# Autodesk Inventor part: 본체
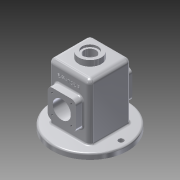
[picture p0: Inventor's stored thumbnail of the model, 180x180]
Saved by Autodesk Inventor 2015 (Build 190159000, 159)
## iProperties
Created: 2021-08
Part Number: 본체
Material: 알루미늄 6061
Document SubType Name: Modeling
Designer: 104-1
Density: 2.7 g/cm^3
Appearance: 알루미늄 - 평지
Mass: 822.027 g
Surface Area: 962.051 cm^2
Volume: 304.454 cm^3
Author: 104-1
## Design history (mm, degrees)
sketch "스케치1"
  geometry: L1 (37, 37)-(-37, 37); L2 (-37, 37)-(-37, -37); L3 (-37, -37)-(37, -37); L4 (37, -37)-(37, 37); L5 (37, 37)-(-37, -37); L6 (-37, 37)-(37, -37); 1 further point
  constraints: 12 end point, 2 midpoint, 2 parallel, 1 horizontal, 1 perpendicular
  dimensions: "d0" = 74 distance of L2.end L3.end; "d1" = 74 distance of L3.end L1.start
extrude "돌출1" new body sketch "스케치1" distance "d2" = 110; taper "d3" = 0 deg
fillet "모깎기1" dims "d4" = 8
fillet "모깎기2" dims "d5" = 8
feature "쉘1" dims "d6" = 5
sketch "스케치2"
  geometry: L1 (-29, 37)-(29, 37) reference; L2 (-37, -29)-(-37, 29) reference; L3 (29, -37)-(-29, -37) reference; L4 (37, 29)-(37, -29) reference; C1 r 67 at (0, 0); A1 r 8 centre (29, 29) between (37, 29) and (29, 37) reference; A2 r 8 centre (-29, 29) between (-29, 37) and (-37, 29) reference; A3 r 8 centre (-29, -29) between (-37, -29) and (-29, -37) reference; A4 r 8 centre (29, -29) between (29, -37) and (37, -29) reference; 1 further point
  constraints: 1 centre point, 1 coincident
  dimensions: "d7" = 134 diameter of C1
extrude "돌출2" join sketch "스케치2" distance "d8" = 10; taper "d9" = 0 deg
sketch "스케치3"
  geometry: L1 (54, -22)-(4, -22); L2 (4, -22)-(4, -72); L3 (4, -72)-(54, -72); L4 (54, -72)-(54, -22); L5 (54, -22)-(4, -72); L6 (4, -22)-(54, -72); L7 (96, -102)-(-38, -102) reference; 4 further points
  constraints: 12 end point, 4 midpoint, 2 parallel, 1 horizontal, 1 perpendicular, 1 vertical alignment
  dimensions: "d10" = 55 distance from line of L7 point (29, -47); "d61" = 50 distance of L1.end L2.end; "d62" = 50 distance of L2.end L3.end
extrude "돌출3" join sketch "스케치3" distance "d11" = 13; taper "d13" = 0 deg; dims "d12" = 12, "d14" = 0
chamfer "모따기1" distance "d15" = 7; stored, may be unused: second distance "d16" = 2, angle "d17" = 20 deg
chamfer "모따기2" distance "d18" = 7; stored, may be unused: second distance "d19" = 2, angle "d20" = 20 deg
chamfer "모따기3" distance "d21" = 7; stored, may be unused: second distance "d22" = 2, angle "d23" = 20 deg
chamfer "모따기4" distance "d24" = 7; stored, may be unused: second distance "d25" = 2, angle "d26" = 20 deg
chamfer "모따기5" distance "d27" = 7; stored, may be unused: second distance "d28" = 2, angle "d29" = 20 deg
chamfer "모따기6" distance "d30" = 7; stored, may be unused: second distance "d31" = 2, angle "d32" = 20 deg
chamfer "모따기7" distance "d33" = 7; stored, may be unused: second distance "d34" = 2, angle "d35" = 20 deg
fillet "모깎기3" dims "d36" = 8
fillet "모깎기4" dims "d37" = 8
chamfer "모따기8" distance "d38" = 7; stored, may be unused: second distance "d39" = 2, angle "d40" = 45 deg
sketch "스케치4"
  geometry: C1 r 67 at (0, 0) reference; 1 further point
  constraints: 1 horizontal alignment
  dimensions: "d41" = 55 distance of C1.centre point (-55, 0)
hole "구멍1" sketch "스케치4" at (-55, 0) diameter "d42" = 9; stored, may be unused: countersink angle "d46" = 90 deg, drill point angle "d48" = 118 deg; dims "d43" = 6, "d44" = 4, "d45" = 2, "d47" = 8
sketch "스케치5"
  geometry: L1 (96, -102)-(-38, -102) reference; L2 (-8, 0)-(-8, -92) reference; 2 further points
  dimensions: "d52" = 55 distance from line of L1 point (29, -47); "d53" = 37 distance from line of L2 point (29, -47)
hole "구멍2" sketch "스케치5" at (29, -47) diameter "d54" = 32; stored, may be unused: countersink angle "d58" = 90 deg, drill point angle "d60" = 118 deg; dims "d55" = 6, "d56" = 4, "d57" = 2, "d59" = 8
sketch "스케치6"
  geometry: A1 r 8 centre (34, -42) between (34, -50) and (42, -42) reference; A2 r 8 centre (34, -8) between (42, -8) and (34, 0) reference; A3 r 8 centre (0, -8) between (0, 0) and (-8, -8) reference; A4 r 8 centre (0, -42) between (-8, -42) and (0, -50) reference; 1 further point
hole "구멍3" sketch "스케치6" at (34, -42), (0, -8), (34, -8), (0, -42) diameter "d63" = 3.242; stored, may be unused: countersink angle "d67" = 90 deg, drill point angle "d69" = 118 deg; dims "d64" = 8, "d65" = 4, "d66" = 2, "d68" = 10
node "작업 평면1"
sketch "스케치8"
  geometry: L1 (29, 29)-(29, -29) reference; L2 (-29, 29)-(29, 29) reference; L3 (-29, -29)-(-29, 29) reference; L4 (29, -29)-(-29, -29) reference; L5 (37, -29)-(37, 29) reference; L6 (29, 37)-(-29, 37) reference; L7 (-37, 29)-(-37, -29) reference; L8 (-29, -37)-(29, -37) reference; C1 r 20 at (0, 0); 1 further point
  constraints: 1 centre point, 1 coincident
  dimensions: "d71" = 40 diameter of C1
extrude "돌출4" join sketch "스케치8" stored distance "d72" = 13; taper "d73" = 0 deg
sketch "스케치9"
  geometry: C1 r 20 at (0, 0) reference
hole "구멍4" sketch "스케치9" at (0, 0) diameter "d74" = 21; stored, may be unused: countersink angle "d78" = 90 deg, drill point angle "d80" = 0 deg; dims "d75" = 8, "d76" = 28, "d77" = 4, "d79" = 10
sketch "스케치10"
  geometry: L1 (-8, 0)-(-8, -92) reference; L2 (9, 18)-(49, 18) reference; 2 further points
  constraints: 1 other
  dimensions: "d81" = 37 distance from line of point (29, -10) L1; "d82" = 28 distance from line of point (29, -10) L2
feature "엠보싱1" sketch "스케치10" dims "d83" = 0.5, "d84" = 0
fillet "모깎기5" dims "d85" = 3
fillet "모깎기6" dims "d86" = 3
fillet "모깎기7" dims "d87" = 3
fillet "모깎기8" dims "d88" = 3
node "솔리드1"
mirror "대칭1"
pattern_circular "원형 패턴1" dims angle "d50" = 360 deg
mirror "대칭2"
node "투영된 루프1"
